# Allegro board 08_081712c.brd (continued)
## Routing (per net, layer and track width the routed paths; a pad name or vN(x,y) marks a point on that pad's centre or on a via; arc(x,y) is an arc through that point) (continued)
DAI0_PIN09_SOM_A: length 122.2
  TOP w0.127: SOMA.45 125.15,68.29 v1(125.15,68.29)
  L8_SIG w0.127: v1(217.29,98.56) 212.93,94.19 212.93,78.9 205.99,71.96 194.92,71.96 189.98,67.02 126.48,67.02 v1(125.15,68.29)
  BOTTOM w0.14: v1(217.29,98.56) 217.29,101.16 218.98,102.85 U36.13
DAI0_PIN09_SOM_B: length 68.2
  TOP w0.127: SOMB.45 v1(252.15,64.27)
  L3_SIG w0.127: v1(227.38,83.13) 227.38,83.13 227.38,84 226.77,84.61 226.77,93.62 219.56,100.84 219.56,101.42 v1(218.03,102.95)
  L8_SIG w0.127: v1(227.38,83.13) 227.38,81.36 233.55,75.18 240.41,75.18 244.6,70.99 244.6,63.63 246.61,61.62 250.93,61.62 252.15,62.84 v1(252.15,64.27)
  BOTTOM w0.203: v1(218.03,102.95) 218.36,102.95 218.77,103.35 U36.14
DAI0_PIN10_SOM_A: length 19.9
  TOP w0.127: SOMA.47 v1(125.64,64.78)
  BOTTOM w0.127: v1(125.64,64.78) 125.64,62.7 127.25,61.09 137.41,61.09 139.26,62.93 R1.1
DAI0_PIN10_SOM_B: length 19.9
  TOP w0.127: SOMB.47 v1(252.64,64.78)
  BOTTOM w0.127: R8.1 266.26,62.93 264.41,61.09 254.25,61.09 252.64,62.7 v1(252.64,64.78)
DAI0_PIN11_SOM_A: length 112.7
  TOP w0.127: P20.1 48.26,89.13 52.53,93.4 79.68,93.4 95.23,77.85 112.22,77.85 113.38,79.01 118.22,79.01 121.39,75.84 SOMA.30
  BOTTOM w0.127: P20.1 42.42,81.41 42.42,71.63 40.89,70.1 39.18,70.1 38.54,70.74 J4.4
DAI0_PIN11_SOM_B: length 145.7
  TOP w0.127: SOMB.30 v1(248.39,77.85)
  L8_SIG w0.127: v1(248.39,77.85) 249.58,77.85 252.4,80.68 253.35,80.68 253.92,81.25 253.92,81.58 254.54,82.2 255.32,82.2 257.83,84.71 273.43,84.71 275.69,82.45 296.8,82.45 304.85,74.4 311.2,74.4 313.37,76.58 325.95,76.58 327.45,75.08 350.98,75.08 353.89,72.18 v1(353.89,71.72)
  BOTTOM w0.127: P3.4 v1(353.89,71.72) 353.89,70.74 354.52,70.1 356.24,70.1 357.76,71.63 357.76,81.41 P39.1
DAI0_PIN12_SOM_A: length 119.4
  TOP w0.127: P20.3 46.71,83.72 46.71,88.29 52.32,93.9 79.88,93.9 95.58,78.21 111.86,78.21 113.17,79.51 118.46,79.51 121.9,76.07 SOMA.32
  BOTTOM w0.127: J4.8 37.27,70.21 38.65,68.83 41.53,68.83 43.56,70.87 43.56,77.47 P20.3
DAI0_PIN12_SOM_B: length 141.8
  TOP w0.127: SOMB.32 v1(248.9,77.11)
  L8_SIG w0.127: v1(352.62,71.72) 352.62,72.18 350.07,74.73 327.3,74.73 325.81,76.22 313.52,76.22 311.34,74.05 304.64,74.05 296.59,82.09 275.51,82.09 273.33,84.27 257.96,84.27 255.45,81.77 254.68,81.77 254.38,81.47 254.38,81.15 253.47,80.24 252.68,80.24 249.55,77.11 v1(248.9,77.11)
  BOTTOM w0.127: P39.3 358.9,77.47 358.9,70.87 356.87,68.83 353.99,68.83 352.62,70.21 v1(352.62,71.72) P3.8
DAI0_PIN13_SOM_A: length 125
  TOP w0.127: P20.5 46.21,79.14 46.21,88.5 52.12,94.4 80.09,94.4 95.9,78.59 111.54,78.59 112.96,80.01 118.7,80.01 122.39,76.31 SOMA.34
  BOTTOM w0.127: P20.5 44.7,73.53 44.7,70.23 42.04,67.56 38.13,67.56 36,69.69 J4.12
DAI0_PIN13_SOM_B: length 138.7
  TOP w0.127: SOMB.34 v1(249.39,76.45)
  L8_SIG w0.127: v1(351.35,71.72) 351.35,72.18 349.15,74.37 327.15,74.37 325.66,75.87 313.67,75.87 311.49,73.69 304.49,73.69 296.45,81.74 275.36,81.74 273.41,83.69 269.49,83.69 268.86,83.06 268.86,82.55 268.18,81.88 267.46,81.88 267.19,81.6 265.69,81.6 264.1,80.01 258.45,80.01 257.46,81 256.64,81 255.52,79.88 252.82,79.88 v1(249.39,76.45)
  BOTTOM w0.127: P39.5 360.05,73.53 360.05,70.23 357.38,67.56 353.47,67.56 351.35,69.69 v1(351.35,71.72) P3.12
DAI0_PIN14_SOM_A: length 129.4
  TOP w0.127: SOMA.36 122.9,76.52 118.83,80.59 94.61,80.59 80.3,94.9 51.91,94.9 45.71,88.7 45.71,74.56 P20.7
  BOTTOM w0.127: J4.16 34.73,69.16 37.6,66.29 42.55,66.29 P20.7
DAI0_PIN14_SOM_B: length 133.1
  TOP w0.127: SOMB.36 v1(249.9,75.82)
  L8_SIG w0.127: v1(249.9,75.82) 250.39,76.32 250.39,76.45 253.42,79.48 255.76,79.48 256.11,79.83 257.22,79.83 257.63,79.43 264.02,79.43 265.84,81.25 267.34,81.25 267.61,81.52 268.46,81.52 269.01,82.07 274.41,82.07 274.94,81.53 275.06,81.53 275.21,81.38 296.3,81.38 304.34,73.33 311.64,73.33 313.81,75.51 325.51,75.51 327.01,74.02 348.24,74.02 350.08,72.18 v1(350.08,71.72)
  BOTTOM w0.127: P39.7 357.89,66.29 352.94,66.29 350.08,69.16 v1(350.08,71.72) P3.16
DAI0_PIN15_SOM_A: length 136.8
  TOP w0.127: SOMA.38 123.39,76.73 119.23,80.9 95.01,80.9 80.51,95.4 51.7,95.4 45.21,88.91 45.21,69.98 P20.9
  BOTTOM w0.127: P20.9 44.96,66.93 43.05,65.02 37.07,65.02 33.46,68.63 J4.20
DAI0_PIN15_SOM_B: length 131.5
  TOP w0.127: SOMB.38 v1(250.39,75.11)
  L8_SIG w0.127: v1(250.39,75.11) 250.75,75.46 250.75,76.3 252.55,78.11 254.89,78.11 256.26,79.48 257.07,79.48 257.48,79.07 268.15,79.07 269.72,80.64 271.96,80.64 272.24,80.92 272.27,80.92 273.06,81.71 274.26,81.71 274.95,81.03 296.1,81.03 304.14,72.98 311.87,72.98 314.04,75.16 325.36,75.16 326.86,73.66 347.33,73.66 348.81,72.18 v1(348.81,71.72)
  BOTTOM w0.127: P39.9 360.3,66.93 358.39,65.02 352.42,65.02 348.81,68.63 v1(348.81,71.72) P3.20
DAI0_PIN16_SOM_A: length 146
  TOP w0.127: SOMA.40 123.9,76.94 119.55,81.28 95.33,81.28 80.71,95.9 51.49,95.9 44.6,89.01 44.6,65.51 P20.11
  BOTTOM w0.127: J4.24 32.19,68.11 36.55,63.75 43.05,63.75 44.96,61.85 P20.11
DAI0_PIN16_SOM_B: length 131.9
  TOP w0.127: v1(251.39,75.91) 251.39,75.42 250.9,74.92 SOMB.40
  L8_SIG w0.127: v1(251.39,75.91) 251.39,76.43 252.6,77.65 256.46,77.65 257.53,78.71 268.46,78.71 270.04,80.29 272.14,80.29 273.21,81.36 274.11,81.36 275.67,79.8 277.67,79.8 278.49,80.62 296,80.62 304,72.62 312.01,72.62 314.19,74.8 325.22,74.8 326.71,73.3 346.41,73.3 347.54,72.18 v1(347.54,71.72)
  BOTTOM w0.127: P39.11 360.3,61.85 358.39,63.75 351.89,63.75 347.54,68.11 v1(347.54,71.72) P3.24
DAI0_PIN17_SOM_A: length 156.6
  TOP w0.127: SOMA.42 124.39,77.14 119.95,81.58 95.74,81.58 80.92,96.4 51.29,96.4 44.1,89.22 44.1,60.93 P20.13
  BOTTOM w0.127: P20.13 42.55,62.48 36.02,62.48 30.92,67.58 J4.28
DAI0_PIN17_SOM_B: length 132.3
  TOP w0.127: v1(252.04,75.97) 252.04,75.54 251.39,74.89 SOMB.42
  L8_SIG w0.127: v1(252.04,75.97) 252.04,76.49 252.64,77.09 252.94,77.09 252.95,77.1 260.24,77.1 261.49,78.36 268.61,78.36 270.18,79.93 272.29,79.93 273.35,81 273.97,81 275.54,79.43 277.8,79.43 278.64,80.26 295.86,80.26 303.85,72.27 312.16,72.27 312.84,72.94 345.5,72.94 346.27,72.18 v1(346.27,71.72)
  BOTTOM w0.127: P3.28 v1(346.27,71.72) 346.27,67.58 351.36,62.48 357.89,62.48 P39.13
DAI0_PIN18_SOM_A: length 169
  TOP w0.127: SOMA.44 124.9,77.35 120.36,81.89 96.14,81.89 81.13,96.9 51.08,96.9 43.6,89.42 43.6,56.35 P20.15
  BOTTOM w0.127: J4.32 29.65,67.05 35.5,61.21 41.78,61.21 46.36,56.64 46.36,53.59 P20.15
DAI0_PIN18_SOM_B: length 133.9
  TOP w0.127: v1(252.74,76) 252.74,75.55 251.9,74.7 SOMB.44
  L8_SIG w0.127: v1(252.74,76) 252.74,76.38 253.1,76.75 264.71,76.75 265.89,77.93 268.68,77.93 270.33,79.58 273.51,79.58 274.29,78.79 294.34,78.79 301.21,71.91 312.31,71.91 312.98,72.59 344.59,72.59 345,72.18 v1(345,71.72)
  BOTTOM w0.127: P3.32 v1(345,71.72) 345,67.05 350.84,61.21 357.12,61.21 361.7,56.64 361.7,53.59 P39.15
DAI0_PIN19_SOM_A: length 140.6
  TOP w0.127: SOMA.46 v1(125.39,74.95) ; v1(17.23,31.62) 32.22,46.61 P20.17
  BOTTOM w0.127: v1(125.39,74.95) 124.34,73.89 100.93,73.89 100.34,73.3 100.3,73.3 64.01,37.01 51.41,37.01 50.29,38.13 50.29,44.58 P20.17
  BOTTOM w0.14: U67.4 v1(17.23,31.62)
DAI0_PIN19_SOM_A_A2B: length 49
  L8_SIG w0.127: v1(28.38,63.93) 28.38,40.07 20.8,32.49 17.09,32.49 v1(16.72,32.12)
  BOTTOM w0.127: J4.36 v1(28.38,63.93)
  BOTTOM w0.14: U67.3 v1(16.72,32.12)
DAI0_PIN19_SOM_B: length 153.6
  TOP w0.127: v1(384.89,31.62) 384.89,32.58 369.65,47.83 364.82,47.83 P39.17 ; SOMB.46 v1(252.39,72.03)
  L8_SIG w0.127: P39.17 361.39,48.82 290.95,48.82 273.1,66.67 258.47,66.67 253.14,72.01 252.41,72.01 v1(252.39,72.03)
  BOTTOM w0.14: U69.4 v1(384.89,31.62)
DAI0_PIN19_SOM_B_A2B: length 64.2
  TOP w0.127: v1(384.39,32.12) 381.24,32.12 368,45.36 361.92,45.36 343.73,63.56 v1(343.73,71.72)
  BOTTOM w0.127: P3.36 v1(343.73,71.72)
  BOTTOM w0.14: U69.3 v1(384.39,32.12)
DAI0_PIN20_SOM_A: length 146.7
  TOP w0.127: SOMA.48 v1(125.9,75.45) ; P20.19 29.06,41.53 18.11,30.58 15.7,30.58 14.58,29.46 10.85,29.46 10.34,29.97 v1(9.52,29.97)
  BOTTOM w0.127: v1(125.9,75.45) 125.9,74.51 124.89,73.51 101.51,73.51 64.3,36.3 51.28,36.3 49.71,37.87 49.71,40.08 P20.19
  BOTTOM w0.14: v1(9.52,29.97) 9.88,29.62 U67.9
DAI0_PIN20_SOM_A_A2B: length 62.7
  L8_SIG w0.127: v1(27.11,64.61) 28.48,64.61 29.41,63.68 29.41,39.42 16.21,26.21 13.18,26.21 11.47,27.92 v1(11.47,30.12)
  BOTTOM w0.127: J4.40 v1(27.11,64.61)
  BOTTOM w0.14: U67.10 v1(11.47,30.12)
DAI0_PIN20_SOM_B: length 148.4
  TOP w0.127: P39.19 364.87,40.26 369.27,40.26 376.05,33.48 376.05,31.11 v1(377.19,29.97) ; SOMB.48 v1(252.9,71.38)
  L8_SIG w0.127: v1(252.9,71.38) 257.98,66.29 272.69,66.29 273.6,65.39 273.6,64.42 275.03,62.99 276,62.99 290.68,48.31 356.82,48.31 P39.19
  BOTTOM w0.14: v1(377.19,29.97) 377.54,29.62 U69.9
DAI0_PIN20_SOM_B_A2B: length 62.3
  TOP w0.127: v1(342.46,71.72) 342.46,63.26 362.84,42.88 368.21,42.88 379.14,31.95 v1(379.14,30.12)
  BOTTOM w0.127: P3.40 v1(342.46,71.72)
  BOTTOM w0.14: U69.10 v1(379.14,30.12)
DAI1_PIN01_SOM_A: length 53.4
  TOP w0.127: SOMA.51 v1(126.64,63.76)
  BOTTOM w0.127: U38.3 110.36,96.16 110.24,96.04 110.24,94.74 112.39,92.58 120.4,92.58 128.02,84.96 129.92,84.96 132.53,82.35 132.53,73.22 127.61,68.31 127.61,64.24 127.14,63.76 v1(126.64,63.76)
DAI1_PIN01_SOM_B: length 222.3
  TOP w0.127: v1(248.77,60.92) 250.46,60.92 253.64,64.11 SOMB.51
  L8_SIG w0.127: 243.48,62.1 244.67,60.92 v1(248.77,60.92)
  L8_SIG w0.14: v1(112.04,95.96) 111.36,96.64 111.36,98.8 112.85,100.29 116.35,100.29 116.96,100.89 131.96,100.89 133.69,99.16 165.65,99.16 173.6,107.11 229.04,107.11 229.51,106.63 237.23,106.63 243.25,100.61 243.25,92.23 241.67,90.65 240.58,90.65 239.52,89.59 232.71,89.59 226.49,83.36 226.49,76.02 227.69,74.82 240.24,74.82 243.48,71.58 243.48,62.1
  BOTTOM w0.14: U38.2 111.74,95.66 v1(112.04,95.96)
DAI1_PIN02_SOM_A: length 52.6
  TOP w0.127: SOMA.53 v1(127.15,64.85)
  BOTTOM w0.127: v1(127.15,64.85) 127.15,68.47 132.08,73.41 132.08,82.17 129.67,84.58 127.76,84.58 120.14,92.2 112.14,92.2 109.6,94.74 109.6,97.41 109.86,97.66 U38.6
DAI1_PIN02_SOM_B: length 220.9
  TOP w0.127: v1(249.57,60.42) 250.5,60.42 254.15,64.06 SOMB.53
  L8_SIG w0.127: v1(249.57,60.42) 244.65,60.42 243.12,61.96 243.12,62.1
  L8_SIG w0.14: 243.12,62.1 243.12,71.43 240.09,74.45 227.54,74.45 226.12,75.87 226.12,83.52 232.56,89.95 239.26,89.95 240.32,91.01 241.35,91.01 242.89,92.55 242.89,100.46 237.46,105.88 231.29,105.88 230.73,105.32 228.57,105.32 227.16,106.74 173.94,106.74 165.86,98.66 133.67,98.66 131.87,100.46 117.21,100.46 116.55,99.79 113.15,99.79 111.91,98.55 v1(111.91,97.16)
  BOTTOM w0.14: U38.5 v1(111.91,97.16)
DAI1_PIN03_SOM_A: length 46.6
  TOP w0.127: SOMA.55 v1(127.64,63.25)
  BOTTOM w0.127: U39.13 131.52,96.66 128.4,93.54 128.4,89.03 129.79,87.63 131.7,87.63 135.38,83.95 135.38,70.48 130.94,66.04 130.94,64.9 129.67,63.63 128.03,63.63 v1(127.64,63.25)
DAI1_PIN03_SOM_B: length 197.9
  TOP w0.127: SOMB.55 254.64,63.85 250.71,59.92 v1(248.77,59.92)
  L8_SIG w0.127: 242.75,62.1 242.75,61.82 244.65,59.92 v1(248.77,59.92)
  L8_SIG w0.14: 242.75,62.1 242.75,71.27 239.94,74.09 227.39,74.09 225.75,75.72 225.75,83.84 233.14,91.23 239.73,91.23 242.52,94.02 242.52,100.31 237.31,105.51 232.07,105.51 231.41,104.85 225.33,104.85 224.56,105.61 218.2,105.61 217.49,106.32 174.23,106.32 166.2,98.29 135.5,98.29 133.71,96.49 v1(133.21,96.49)
  BOTTOM w0.14: U39.14 132.88,96.16 v1(133.21,96.49)
DAI1_PIN04_SOM_A: length 53
  TOP w0.127: SOMA.57 v1(128.15,64.27)
  BOTTOM w0.127: v1(128.15,64.27) 128.15,68.07 132.97,72.9 132.97,82.55 130.17,85.34 128.14,85.34 120.52,92.96 113.54,92.96 112.78,93.73 112.78,97.51 113.43,98.16 U38.10
DAI1_PIN04_SOM_B: length 220.4
  TOP w0.127: v1(249.57,59.42) 250.92,59.42 255.15,63.65 SOMB.57
  L8_SIG w0.127: v1(249.57,59.42) 244.65,59.42 242.38,61.69 242.38,62.1
  L8_SIG w0.14: v1(113.68,97.66) 114.97,98.96 121.77,98.96 122.13,99.32 129.6,99.32 132.98,95.94 133.89,95.94 135.87,97.92 166.54,97.92 174.56,105.95 217.34,105.95 218.04,105.24 224.41,105.24 225.18,104.48 231.56,104.48 232.22,105.14 237.16,105.14 242.15,100.15 242.15,94.17 239.58,91.6 232.89,91.6 225.39,84.1 225.39,75.57 227.24,73.72 239.78,73.72 242.38,71.12 242.38,62.1
  BOTTOM w0.14: U38.11 v1(113.68,97.66)
DAI1_PIN05_SOM_A: length 50.3
  TOP w0.127: SOMA.59 v1(128.64,64.78)
  BOTTOM w0.127: U38.13 113.45,96.66 113.16,96.37 113.16,93.98 113.79,93.34 120.78,93.34 128.4,85.72 130.43,85.72 133.42,82.74 133.42,72.61 128.64,67.84 v1(128.64,64.78)
DAI1_PIN05_SOM_B: length 219.9
  TOP w0.127: v1(248.77,58.92) 251.13,58.92 255.64,63.44 SOMB.59
  L8_SIG w0.127: 242.01,62.1 242.01,61.56 244.65,58.92 v1(248.77,58.92)
  L8_SIG w0.14: 242.01,62.1 242.01,70.97 239.63,73.35 227.08,73.35 225.02,75.41 225.02,84.25 232.74,91.97 238.17,91.97 240.82,94.61 240.82,98.2 240.02,99 240.02,101.76 237.01,104.77 232.38,104.77 231.71,104.11 225.03,104.11 224.29,104.85 190.91,104.85 190.88,104.88 174.47,104.88 167.08,97.49 135.95,97.49 134.04,95.57 132.7,95.57 129.32,98.95 126.01,98.95 125.15,98.09 121.01,98.09 120.73,98.37 118.77,98.37 117.98,97.59 115.1,97.59 v1(113.68,96.16)
  BOTTOM w0.14: U38.14 v1(113.68,96.16)
DAI1_PIN06_SOM_A: length 44.3
  TOP w0.127: SOMA.61 v1(129.15,64.27)
  BOTTOM w0.127: v1(129.15,64.27) 129.73,64.27 130.3,64.85 130.3,66.17 135,70.87 135,83.69 131.44,87.25 129.54,87.25 128.02,88.77 128.02,93.34 124.97,96.39 124.97,97.41 124.74,97.64 U40.3
DAI1_PIN06_SOM_B: length 209.4
  TOP w0.127: SOMB.61 256.15,63.23 251.33,58.42 v1(249.57,58.42)
  L8_SIG w0.127: v1(249.57,58.42) 244.64,58.42 241.64,61.42 241.64,62.1
  L8_SIG w0.14: v1(125.48,96.65) 127.43,96.65 128.51,97.73 130.02,97.73 132.54,95.21 134.2,95.21 136.11,97.12 167.23,97.12 174.59,104.48 224.14,104.48 224.87,103.74 231.86,103.74 232.53,104.41 236.85,104.41 239.65,101.61 239.65,98.59 240.45,97.79 240.45,94.77 238.02,92.34 232.57,92.34 224.65,84.42 224.65,75.26 226.93,72.98 239.48,72.98 241.64,70.82 241.64,62.1
  BOTTOM w0.14: v1(125.48,96.65) 125.48,97.66 125,98.14 U40.2
DAI1_PIN07_SOM_A: length 40.7
  TOP w0.127: SOMA.63 v1(129.64,64.85)
  BOTTOM w0.127: v1(129.64,64.85) 129.64,66.27 134.62,71.25 134.62,83.44 131.19,86.87 129.29,86.87 127.64,88.52 127.64,93.09 124.59,96.14 U40.6
DAI1_PIN07_SOM_B: length 205.9
  TOP w0.127: v1(248.77,57.92) 251.54,57.92 256.64,63.03 SOMB.63
  L8_SIG w0.127: 241.27,62.1 241.27,61.29 244.64,57.92 v1(248.77,57.92)
  L8_SIG w0.14: v1(122.91,96.64) 126.44,93.11 135.93,93.11 136.84,94.01 165.73,94.01 172.02,100.3 236.21,100.3 239.03,97.49 239.5,97.49 240.08,96.9 240.08,94.92 237.86,92.7 232.39,92.7 224.28,84.6 224.28,75.11 226.78,72.61 239.33,72.61 241.27,70.66 241.27,62.1
  BOTTOM w0.14: U40.5 v1(122.91,96.64)
DAI1_PIN08_SOM_A: length 39.8
  TOP w0.127: SOMA.65 v1(130.15,67.62)
  BOTTOM w0.127: v1(130.15,67.62) 134.24,71.72 134.24,83.19 130.94,86.49 128.91,86.49 121.16,94.23 120.02,94.23 119.47,94.78 119.47,95.47 119.64,95.64 U40.10
DAI1_PIN08_SOM_B: length 207
  TOP w0.127: v1(249.55,57.45) 251.78,57.45 257.15,62.82 SOMB.65
  L8_SIG w0.127: v1(249.55,57.45) 244.61,57.45 240.91,61.15 240.91,62.1
  L8_SIG w0.14: 240.91,62.1 240.91,70.51 239.17,72.24 226.62,72.24 223.91,74.96 223.91,84.82 232.16,93.07 237.6,93.07 238.54,94.01 238.54,97.33 235.93,99.93 172.18,99.93 165.89,93.64 137.08,93.64 136.18,92.74 124.54,92.74 v1(121.15,96.14)
  BOTTOM w0.14: U40.11 v1(121.15,96.14)
DAI1_PIN09_SOM_A: length 41.5
  TOP w0.127: v1(130.17,68.45) 130.64,67.98 SOMA.67
  BOTTOM w0.127: v1(130.17,68.45) 133.86,72.14 133.86,82.93 130.68,86.11 128.65,86.11 120.9,93.85 119.89,93.85 119,94.74 119,96.65 119.49,97.14 U40.13
DAI1_PIN09_SOM_B: length 210.2
  TOP w0.127: v1(248.82,56.9) 251.93,56.9 257.64,62.61 SOMB.67
  L8_SIG w0.127: v1(248.82,56.9) 244.66,56.9 240.54,61.02 240.54,62.1
  L8_SIG w0.14: v1(119.51,97.64) 119.51,97 124.17,92.33 136.42,92.33 137.27,93.17 165.94,93.17 171.95,99.19 236.07,99.19 238.17,97.08 238.17,94.2 237.41,93.44 232.01,93.44 223.54,84.98 223.54,74.8 226.47,71.88 239.02,71.88 240.54,70.36 240.54,62.1
  BOTTOM w0.14: U40.14 v1(119.51,97.64)
DAI1_PIN10_SOM_A: length 97.9
  TOP w0.127: SOMA.69 v1(131.15,64.27) ; v1(180.84,121.41) 180.52,121.72 U81.10
  BOTTOM w0.127: v1(131.15,64.27) 131.15,63.83 131.44,63.53 132.71,63.53 133.12,63.93 133.12,66.22 140.92,74.02 145.19,74.02 146.3,75.13 146.3,76.71 148.46,78.87 148.46,88.87 149.33,89.74 149.33,110.77 159.23,120.68 180.1,120.68 v1(180.84,121.41)
DAI1_PIN10_SOM_B: length 136.9
  TOP w0.127: v1(180.84,119.89) 180.12,120.6 U81.9 ; SOMB.69 v1(258.15,64.27)
  L8_SIG w0.127: v1(258.15,64.27) 257.27,64.27 250.7,70.84 250.7,74.03 244.52,80.21 239.01,80.21 238.88,80.34 238.88,82.29 240.07,83.48 245.17,83.48 v1(250.28,88.58)
  BOTTOM w0.127: v1(180.84,119.89) 183.63,117.09 196.57,117.09 212.09,101.57 212.09,96.01 212.42,95.68 230.86,95.68 233.22,98.04 241.88,98.04 242.42,97.51 242.42,96.45 v1(250.28,88.58)
DAI1_PIN11_SOM_A: length 103.5
  TOP w0.127: SOMA.52 v1(126.9,75.45)
  L8_SIG w0.127: v1(91.25,71.72) 91.67,71.3 100.03,71.3 103.02,74.3 114.99,74.3 117.47,76.78 125.56,76.78 v1(126.9,75.45)
  BOTTOM w0.127: P21.1 54.61,41.91 54.61,49.53 61.34,56.26 82.14,56.26 91.25,65.37 v1(91.25,71.72) J5.4
DAI1_PIN11_SOM_B: length 201.1
  TOP w0.127: SOMB.52 v1(253.9,75.38)
  L8_SIG w0.127: P40.1 365.61,37.57 363.09,37.57 353.39,47.27 289.44,47.27 272.86,63.85 272.86,65.12 272.43,65.56 256.85,65.56 251.26,71.16 251.26,72.74 v1(253.9,75.38)
  BOTTOM w0.127: P4.4 406.59,65.37 397.48,56.26 376.68,56.26 369.95,49.53 369.95,41.91 P40.1
DAI1_PIN12_SOM_A: length 97.8
  TOP w0.127: SOMA.54 v1(127.39,74.95)
  L8_SIG w0.127: v1(127.39,74.95) 126.34,73.89 103.23,73.89 99.67,70.33 v1(89.98,70.33)
  BOTTOM w0.127: P21.3 53.59,45.97 53.59,49.78 61.34,57.53 81.62,57.53 89.98,65.89 v1(89.98,70.33) J5.8
DAI1_PIN12_SOM_B: length 194.1
  TOP w0.127: SOMB.54 v1(254.39,74.87)
  L8_SIG w0.127: v1(254.39,74.87) 251.76,72.24 251.76,71.65 257.51,65.91 272.57,65.91 273.22,65.27 273.22,64.09 274.83,62.48 275.46,62.48 290.17,47.78 354.08,47.78 361.57,40.28 364.87,40.28 365.35,40.77 365.35,42.39 P40.3
  BOTTOM w0.127: P4.8 405.32,65.89 396.96,57.53 376.68,57.53 368.94,49.78 368.94,45.97 P40.3
DAI1_PIN13_SOM_A: length 95.5
  TOP w0.127: SOMA.56 v1(127.9,75.45)
  L8_SIG w0.127: v1(88.71,71.72) 88.71,72.18 89.12,72.59 100.58,72.59 102.64,74.65 114.81,74.65 117.35,77.19 126.16,77.19 v1(127.9,75.45)
  BOTTOM w0.127: J5.12 v1(88.71,71.72) 88.71,66.42 81.09,58.8 61.34,58.8 P21.5
DAI1_PIN13_SOM_B: length 175.5
  TOP w0.127: SOMB.56 v1(254.9,71.45)
  L8_SIG w0.127: P40.5 365.91,50.27 363.14,50.27 362.25,49.38 291.03,49.38 273.23,67.18 258.7,67.18 254.9,70.99 v1(254.9,71.45)
  BOTTOM w0.127: P40.5 376.68,58.8 396.43,58.8 404.05,66.42 P4.12
DAI1_PIN14_SOM_A: length 91.9
  TOP w0.127: SOMA.58 v1(128.39,74.95)
  L8_SIG w0.127: v1(87.44,69.79) 99.78,69.79 103.5,73.51 126.96,73.51 v1(128.39,74.95)
  BOTTOM w0.127: J5.16 v1(87.44,69.79) 87.44,66.95 80.56,60.07 61.34,60.07 55.5,54.23 P21.7
DAI1_PIN14_SOM_B: length 172
  TOP w0.127: SOMB.58 v1(255.39,72.03)
  L8_SIG w0.127: v1(255.39,72.03) 255.65,71.77 255.65,70.87 258.88,67.64 273.35,67.64 291.13,49.86 357.58,49.86 360.53,52.81 365.61,52.81 P40.7
  BOTTOM w0.127: P4.16 402.78,66.95 395.91,60.07 376.68,60.07 370.84,54.23 P40.7
DAI1_PIN15_SOM_A: length 92.2
  TOP w0.127: SOMA.60 v1(128.9,75.45)
  L8_SIG w0.127: v1(128.9,75.45) 126.68,77.67 117.33,77.67 114.79,75.13 102.62,75.13 100.49,73 86.69,73 86.17,72.48 v1(86.17,71.72)
  BOTTOM w0.127: J5.20 v1(86.17,71.72) 86.17,67.47 80.04,61.34 61.34,61.34 59.31,59.31 P21.9
DAI1_PIN15_SOM_B: length 174.3
  TOP w0.127: SOMB.60 v1(255.9,75.38)
  L8_SIG w0.127: P40.9 365.38,57.66 365.38,56.64 364.08,55.35 362.31,55.35 357.38,50.42 291.47,50.42 279.65,62.23 279.65,63.04 274.57,68.12 259.16,68.12 256.01,71.27 256.01,73.94 255.65,74.3 255.65,75.13 v1(255.9,75.38)
  BOTTOM w0.127: P40.9 374.65,59.31 376.68,61.34 395.38,61.34 401.51,67.47 P4.20
DAI1_PIN16_SOM_A: length 89.4
  TOP w0.127: SOMA.62 v1(129.39,74.95)
  L8_SIG w0.127: v1(84.9,69.27) 84.92,69.24 99.95,69.24 103.84,73.13 127.57,73.13 v1(129.39,74.95)
  BOTTOM w0.127: J5.24 v1(84.9,69.27) 84.9,68.75 78.77,62.61 60.96,62.61 59.18,64.39 P21.11
DAI1_PIN16_SOM_B: length 174.8
  TOP w0.127: SOMB.62 v1(256.39,74.87)
  L8_SIG w0.127: P40.11 365.84,63.2 363.17,63.2 361.87,61.9 361.87,55.68 357.2,51 291.52,51 281.18,61.34 281.18,62.15 274.82,68.5 259.79,68.5 256.39,71.9 v1(256.39,74.87)
  BOTTOM w0.127: P40.11 374.52,64.39 376.3,62.61 394.85,62.61 400.24,68 P4.24
DAI1_PIN17_SOM_A: length 14.3
  TOP w0.127: SOMA.64 v1(129.9,76.2)
  BOTTOM w0.127: v1(129.9,76.2) 128.63,77.47 123.95,77.47 121.17,80.26 R400.1
DAI1_PIN17_SOM_A_A2B: length 88.4
  L8_SIG w0.127: v1(125.03,80.97) 125.03,80.05 123.8,78.82 114.63,78.82 113.26,77.44 101.5,77.44 98.96,74.9 85.6,74.9 83.63,72.94 v1(83.63,71.72)
  BOTTOM w0.127: P21.13 55.37,69.47 61.32,63.53 77.24,63.53 83.63,69.91 v1(83.63,71.72) J5.28 ; U45.3 v1(125.03,80.97)
DAI1_PIN17_SOM_B: length 14.3
  TOP w0.127: SOMB.64 v1(256.9,76.2)
  BOTTOM w0.127: v1(256.9,76.2) 255.85,77.24 251.18,77.24 248.17,80.26 R412.2
DAI1_PIN17_SOM_B_A2B: length 199.2
  TOP w0.127: v1(320.65,90.32) 333.27,90.32 333.88,89.71 358.8,89.71 360.94,91.85 367.51,91.85 370.13,89.23 370.13,72.57 P40.13
  L8_SIG w0.127: v1(251.33,80.97) 250.78,81.52 250.78,83.7 251.1,84.02 251.55,84.02 251.75,83.82 252.94,83.82 253,83.88 253.87,83.88 254.12,84.12 254.19,84.12 254.42,84.36 255.46,84.36 257.24,86.13 275.55,86.13 277.81,83.87 297.94,83.87 304.57,77.24 309.62,77.24 310.79,78.42 310.79,81.1 320.01,90.32 v1(320.65,90.32)
  BOTTOM w0.127: P4.28 398.97,68.53 394.33,63.88 376.3,63.88 370.71,69.47 P40.13 ; U47.3 v1(251.33,80.97)
DAI1_PIN18_SOM_A: length 16.7
  TOP w0.127: SOMA.66 v1(130.39,74.87)
  BOTTOM w0.127: R401.1 120.4,82.22 120.4,80.26 123.7,76.96 128.3,76.96 v1(130.39,74.87)
DAI1_PIN18_SOM_A_A2B: length 89.7
  L8_SIG w0.127: v1(124.49,82.47) 124.49,80.19 123.47,79.17 114.45,79.17 113.11,77.83 101.27,77.83 98.86,75.41 84.58,75.41 82.36,73.19 v1(82.36,71.72)
  BOTTOM w0.127: J5.32 v1(82.36,71.72) 82.36,70.02 77.42,65.07 61.16,65.07 P21.15 ; U45.6 v1(124.49,82.47)
DAI1_PIN18_SOM_B: length 16.7
  TOP w0.127: SOMB.66 v1(257.39,74.87)
  BOTTOM w0.127: v1(257.39,74.87) 255.38,76.89 250.77,76.89 247.4,80.26 247.4,82.22 R413.2
DAI1_PIN18_SOM_B_A2B: length 189.1
  TOP w0.127: P40.15 369.57,77.09 369.57,89.13 367.31,91.39 361.13,91.39 358.87,89.12 333.82,89.12 333.27,89.66 v1(320.65,89.66)
  L8_SIG w0.127: v1(320.65,89.66) 320.08,89.66 311.28,80.86 311.28,78.24 309.92,76.89 304.32,76.89 297.69,83.52 277.66,83.52 275.4,85.78 257.38,85.78 255.61,84 254.57,84 254.34,83.77 254.26,83.77 254.02,83.52 253.15,83.52 252.94,83.31 252.86,83.31 252.02,82.47 v1(251.33,82.47)
  BOTTOM w0.127: P40.15 376.43,65.15 393.8,65.15 397.7,69.05 P4.32 ; U47.6 v1(251.33,82.47)
DAI1_PIN19_SOM_A: length 11.1
  TOP w0.127: SOMA.68 v1(130.9,75.45)
  BOTTOM w0.127: R402.1 131.57,81.46 131.57,76.13 v1(130.9,75.45)
DAI1_PIN19_SOM_A_A2B: length 95.5
  L8_SIG w0.127: v1(81.09,71.72) 81.09,72.96 84.02,75.9 98.71,75.9 101.02,78.21 112.98,78.21 114.33,79.55 123.14,79.55 123.83,80.24 123.83,82.93 124.26,83.36 125.98,83.36 v1(126.37,82.97)
  BOTTOM w0.127: P21.17 53.34,77.98 53.34,74.42 61.87,65.89 76.84,65.89 81.09,70.14 v1(81.09,71.72) J5.36 ; U45.10 v1(126.37,82.97)
DAI1_PIN19_SOM_B: length 11.1
  TOP w0.127: SOMB.68 v1(257.9,75.45)
  BOTTOM w0.127: R414.2 258.57,81.46 258.57,76.13 v1(257.9,75.45)
DAI1_PIN19_SOM_B_A2B: length 181.8
  TOP w0.127: P40.17 369.06,81.66 369.06,88.9 367.2,90.76 361.39,90.76 359.13,88.49 333.56,88.49 333.05,89 v1(320.65,89)
  L8_SIG w0.127: v1(320.65,89) 320.12,89 311.71,80.59 311.71,78.17 310.07,76.53 304,76.53 297.38,83.16 277.52,83.16 275.25,85.42 257.53,85.42 255.76,83.65 254.72,83.65 254.48,83.41 254.41,83.41 253.97,82.97 v1(253.37,82.97)
  BOTTOM w0.127: P40.17 368.68,77.98 368.68,74.42 376.68,66.42 393.27,66.42 396.43,69.58 P4.36 ; U47.10 v1(253.37,82.97)
DAI1_PIN20_SOM_A: length 9.3
  TOP w0.127: v1(130.94,76.2) 131.39,75.74 SOMA.70
  BOTTOM w0.127: v1(130.94,76.2) 130.94,80.57 R403.1
DAI1_PIN20_SOM_A_A2B: length 102.3
  L8_SIG w0.127: v1(126.37,81.47) 127.05,82.15 127.05,83.46 126.64,83.87 124,83.87 123.29,83.16 123.29,80.37 122.83,79.91 114.18,79.91 112.86,78.59 100.81,78.59 98.53,76.3 82.93,76.3 79.82,73.19 v1(79.82,71.72)
  BOTTOM w0.127: U45.13 v1(126.37,81.47) ; J5.40 v1(79.82,71.72) 79.82,70.35 76.2,66.73 62.31,66.73 54.48,74.55 54.48,81.91 P21.19
DAI1_PIN20_SOM_B: length 9.3
  TOP w0.127: SOMB.70 258.39,75.74 v1(257.94,76.2)
  BOTTOM w0.127: v1(257.94,76.2) 257.94,80.57 R415.2
DAI1_PIN20_SOM_B_A2B: length 177.8
  TOP w0.127: v1(320.65,88.34) 332.59,88.34 333.05,87.88 359.64,87.88 361.72,89.97 367.24,89.97 368.68,88.53 368.68,86.36 P40.19
  L8_SIG w0.127: v1(253.37,81.47) 253.37,81.87 254.56,83.06 254.63,83.06 254.86,83.29 255.91,83.29 257.68,85.06 275.11,85.06 277.37,82.8 297.15,82.8 303.83,76.12 310.24,76.12 312.12,78 312.12,80.34 320.12,88.34 v1(320.65,88.34)
  BOTTOM w0.127: U47.13 v1(253.37,81.47) ; P40.19 369.82,81.91 369.82,74.55 376.68,67.69 392.75,67.69 395.16,70.1 P4.40
DAI1_ROUTE: length 271.7
  TOP w0.127: U8.12 27.58,112.99 v1(26.67,112.08) R512.1
  L3_SIG w0.127: v1(249.22,79.97) 246.01,79.97 240.08,74.04 217.6,74.04 211.37,80.28 195.87,80.28 192.92,83.22 157.94,83.22 154.35,79.63 150.66,79.63 149.89,78.86 149.89,78.86 149.84,78.82 147.94,78.82 146.41,77.29 138.56,77.29 138.44,77.18 133.31,77.18 132.11,78.38 123.77,78.38 121.97,80.19 121.97,85.6 123.27,86.89 v1(123.27,88.19)
  L8_SIG w0.127: v1(123.27,88.19) 119.3,92.15 113.19,92.15 109.86,95.49 109.86,96.77 106.3,100.33 66.55,100.33 56.52,110.36 26.19,110.36 25.83,110.72 25.83,111.81 26.1,112.08 v1(26.67,112.08)
  BOTTOM w0.127: R512.1 v1(26.67,112.08) ; v1(123.27,88.19) 125.6,85.85 125.6,80.26 125.31,79.97 U45.1 ; U47.1 v1(249.22,79.97)
E70_3V3: length 67.7
  TOP w0.14: DS20.A v1(197.61,26.01) ; R484.1 v1(190.88,28.6) ; R485.1 v1(196.21,29.11)
  TOP w0.203: U58.3 U58.2 213.38,33.9 213.18,34.1 U58.1 211.72,34.1 C367.1 ; U59.1 219.76,20.67 219.56,20.46 v1(219.13,20.46) ; U55.3 v1(224.03,12.26) ; U59.7 219.76,23.62 C363.1 ; U59.10 218.64,21.51 218.44,21.3 v1(218.44,20.64)
  TOP w0.305: R484.1 191.45,29.21 192.22,28.44 U56.4 192.74,28.44 193.05,28.14 C353.1 ; R466.1 v1(196.81,35.62) ; R469.1 v1(208.06,35.62) ; R467.1 v1(196.81,34.35) ; U53.8 C325.1 206.51,36.97 ; R464.1 v1(196.81,36.89) ; R470.1 v1(199.78,14.77)
  TOP w0.508: P29.1 200.54,29.65 C322.1 ; C353.1 v1(192.3,26.86) ; D12.4 193.09,21.49 C321.1 v1(192.3,21.53) ; R486.1 v1(216.83,12.26) ; TP24.1 227.18,6.29 ; TP24.1 226.06,7.4 ; TP24.1 224.94,6.29 ; v1(206.51,38.82) C326.1 206.51,36.97 ; R475.1 v1(205.61,14.61) ; R471.1 v1(198.62,23.94) ; P10.1 v1(227.2,19.11) ; C355.1 v1(218.87,15.05) ; C367.1 v1(210.67,33.84) ; P34.1 v1(192.02,7.28) ; R468.1 v1(198.62,22.8) ; C363.1 v1(219.45,24.8)
  L5_PWR w0.508: 224.94,6.29 TP24.1 ; TP24.1 226.06,7.4 ; TP24.1 227.18,6.29 ; TP24.1 226.06,5.17 ; P29.1 201.71,29.65 ; P29.1 199.35,29.65 ; P29.1 200.53,28.47 ; P29.1 200.53,30.84 ; 193.04,22.88 P28.2 ; P28.2 193.04,25.25 ; P28.2 194.22,24.07 ; P28.2 191.86,24.07
  BOTTOM w0.203: C348.1 209.68,18.28 v2(209.05,18.91) ; C354.1 206.63,23.52 206.63,21.91 206.83,21.71 v2(207.05,21.71) ; C364.1 194.93,37.53 U60.1 ; v2(207.05,19.31) 207.05,19.92 C346.1
  BOTTOM w0.508: v1(204.84,14.59) C352.1 C358.1 ; C349.1 C348.1 C350.1 ; E3.1 210.7,21.63 C324.1 C357.1 v1(210.03,23.69) ; C364.1 v1(195.91,37.27)
  vias: v2(205.45,20.11) v2(207.84,19.31) v2(207.84,18.51)
E70_FLASH_CS_N: length 24.6
  TOP w0.14: R464.2 v1(198.67,36.89) U53.1
  L3_SIG w0.114: v2(205.45,22.91) 205.45,24.17 204.85,24.77 204.85,29.08 206.88,31.12 206.88,31.81 206.44,32.26 200.53,32.26 199.17,33.62 198.34,33.62 197.99,33.97 197.99,36.22 v1(198.67,36.89)
E70_FLASH_D2: length 31.2
  TOP w0.14: R467.2 v1(198.67,34.35) U53.3
  L3_SIG w0.114: v1(198.67,34.35) 204.03,34.35 205.87,36.2 206.73,36.2 207.26,35.66 207.26,34.04 211.82,29.48 211.82,25.65 211.07,24.9 208.67,24.9 207.39,23.62 207.39,22.58 208.15,21.82 208.15,21.62 v2(207.84,21.31)
E70_FLASH_D3: length 24.4
  TOP w0.14: R469.2 v1(206.21,35.62) U53.7
  L3_SIG w0.114: v1(206.21,35.62) 205.49,34.9 205.49,34.1 207.64,31.94 207.64,30.1 206.12,28.57 206.12,27.18 205.49,26.54 205.49,25.15 206.63,24 206.63,21.4 207.01,21.02 207.94,21.02 208.19,21.27 209.07,21.27 209.41,20.93 209.41,19.61 209.17,19.37 208.7,19.37 v2(208.24,18.91)
E70_FLASH_MISO: length 12.1
  TOP w0.14: v1(206.25,31.43) 206.25,32.78 205.94,33.08 U53.5
  L3_SIG w0.114: v1(206.25,31.43) 204.34,29.53 204.34,24.57 205.05,23.87 v2(205.05,22.91)
E70_FLASH_MOSI: length 31
  TOP w0.14: U53.2 v1(198.67,35.62) R466.2
  L3_SIG w0.114: v2(207.84,22.51) 208.28,22.95 208.28,23.88 208.81,24.41 211.48,24.41 212.34,25.27 212.34,29.85 209.04,33.15 209.04,35.69 208.57,36.16 207.55,36.16 206.88,36.83 205.36,36.83 204.15,35.62 v1(198.67,35.62)
E70_FLASH_SCK: length 15.6
  TOP w0.14: U53.6 v1(206.21,34.35) R465.1
  L3_SIG w0.114: v2(207.05,22.51) 207.05,24.62 206.22,25.44 206.22,26.27 206.76,26.8 206.76,27.94 208.41,29.59 208.41,32.16 v1(206.21,34.35)
E70_RESET_N: length 44.1
  TOP w0.114: R487.2 197.53,30.92 196.96,30.35 R485.2 194.56,30.35 U56.2
  TOP w0.14: R487.2 v1(198.44,30.92) ; v1(198.41,15.51) R470.2 197.59,14.77 197.1,14.29 P34.10
  L8_SIG w0.114: v1(198.41,15.51) 197.19,14.29 191.9,14.29 191.48,14.7 191.48,15.43 196.57,20.51 202.82,20.51 204.02,21.71 v2(204.65,21.71)
  BOTTOM w0.114: v2(204.65,21.71) 204.41,21.71 203.45,22.67 202.18,22.67 198.44,26.42 v1(198.44,30.92)
E70_SWCLK/TCK: length 15.2
  TOP w0.14: P34.4 v1(193.29,15.2)
  L8_SIG w0.114: v2(204.24,20.91) 203.08,19.75 197.84,19.75 v1(193.29,15.2)
E70_SWDIO/TMS: length 17.6
  TOP w0.14: P34.2 v1(192.02,15.2)
  L8_SIG w0.114: v2(205.05,21.71) 204.61,21.27 204.09,21.27 202.95,20.13 196.95,20.13 v1(192.02,15.2)
E70_TARGET_RESET_N: length 1.9
  TOP w0.14: R484.2 191.71,29.85 192.22,30.36 U56.3
E70_TDI: length 16.3
  TOP w0.14: P34.8 v1(195.83,15.2)
  L8_SIG w0.114: v2(204.24,18.91) 199.44,18.91 198.55,18.02 196.62,18.02 194.02,15.43 194.02,14.83 194.22,14.63 195.26,14.63 v1(195.83,15.2)
E70_TRACESW0/TDO: length 13.5
  TOP w0.14: P34.6 v1(194.56,15.2)
  L8_SIG w0.114: v1(194.56,15.2) 196.82,17.46 198.63,17.46 199.64,18.48 204.21,18.48 v2(204.65,18.91)
E70_USBDM: length 19.3
  TOP w0.102: P9.A7 207.89,11.43 207.77,11.56 207.77,11.89 207.94,12.07 209.74,12.07 210.17,12.5 210.17,13.89 209.5,14.57 207.84,14.57 207.52,14.25 207.52,13.67 207.42,13.57 v1(207,13.57)
  BOTTOM w0.102: v2(207.45,18.11) 207.45,17.86 207.52,17.79 207.52,16.18 207,15.65 D13.1 v1(207,13.57) 207.42,13.57 207.52,13.47 207.52,10.06 207.24,9.78 P9.B7
E70_USBDP: length 19.4
  TOP w0.102: P9.A6 207.4,11.43 207.52,11.56 207.52,11.99 207.84,12.31 208.66,12.31 208.76,12.41 208.76,12.8 208.87,12.9 209.12,12.9 209.22,12.8 209.22,12.41 209.32,12.31 209.64,12.31 209.93,12.6 209.93,13.79 209.4,14.33 207.94,14.33 207.77,14.15 207.77,13.67 207.87,13.57 v1(208.29,13.57)
  BOTTOM w0.102: P9.B6 208.05,9.78 207.77,10.06 207.77,13.47 207.87,13.57 v1(208.29,13.57) D13.3 208.29,15.65 207.77,16.18 207.77,17.79 207.84,17.86 v2(207.84,18.11)
E70_VBG: length 3.1
  TOP w0.203: U54.A3 208.24,17.04 208.92,16.36 C323.1
  TOP w0.508: C323.1 R463.1
E70_VDDCORE: length 9.2
  BOTTOM w0.203: C332.1 207.45,21.33 v2(207.45,21.71) 207.45,22.99 207.45,23 C331.1
  BOTTOM w0.508: v1(201.92,21.78) C337.1 C330.1 C328.1 201.96,18.83 E4.2 ; C340.1 v1(205.64,17.46) ; v1(209.9,19.72) E5.2 211.68,19.72 211.72,19.76 C334.1
  vias: v2(205.45,20.51) v2(207.45,19.31) v2(207.84,19.71)
EEPROM_WP: length 154.3
  TOP w0.127: v1(152.46,92.01) R590.1 151.76,90.79 S15.1
  L3_SIG w0.127: v1(279.59,84.49) 271.19,92.89 248.18,92.89 241.48,86.18 235.53,86.18 229.44,80.09 225.42,80.09 212.93,92.58 153.03,92.58 v1(152.46,92.01)
  BOTTOM w0.127: v1(152.46,92.01) 152.46,84.65 152.59,84.52 U76.5
  BOTTOM w0.14: U10.5 v1(279.59,84.49)
ETH0_LINK_LED: length 25.7
  TOP w0.127: R80.2 129.66,37.47 132.33,34.8 140.33,34.8 141.09,34.04 R82.2
  TOP w0.14: R80.2 v1(130.36,39.37)
  BOTTOM w0.14: U1.21 133.01,41.19 131.19,39.37 v1(130.36,39.37) R80.2
ETH0_MD_INT_SOM_A: length 29.9
  TOP w0.127: SOMA.75 v1(132.64,64.85)
  L3_SIG w0.127: v1(132.64,64.85) 132.09,65.41 131.21,65.41 123.77,57.96 v1(123.77,42.54)
  BOTTOM w0.14: v1(123.77,42.54) U11.4
ETH0_MD_INT_Z: length 10.8
  BOTTOM w0.14: U1.22 132.36,41.69 131.45,40.77 R78.2 129.66,40.7 129.03,40.07 124.4,40.07 124.27,40.2 U11.2
ETH0_MDC_SOM_A: length 49
  TOP w0.127: SOMA.125 v1(145.14,64.78)
  L3_SIG w0.127: v1(130.36,41.85) 131.8,43.29 131.8,44.96 132.31,45.47 141.73,45.47 144.02,47.75 150.24,47.75 151.38,48.89 151.38,58.54 v1(145.14,64.78)
  BOTTOM w0.127: U1.23 130.7,42.19 v1(130.36,41.85)
  BOTTOM w0.14: R62.1 v1(130.36,41.85)
ETH0_MDIO_SOM_A: length 47.5
  TOP w0.127: SOMA.123 v1(144.65,64.27)
  L3_SIG w0.127: v1(130.36,42.93) 131.06,43.64 131.06,45.27 132,46.2 141.43,46.2 143.71,48.49 149.94,48.49 150.65,49.2 150.65,58.24 144.65,64.24 v1(144.65,64.27)
  BOTTOM w0.127: v1(130.36,42.93) 130.63,42.66 133.59,42.66 U1.24
  BOTTOM w0.14: R81.2 v1(130.36,42.93)
ETH0_MDIX_MODE: length 5
  TOP w0.127: R75.2 v1(130.36,45.09)
  BOTTOM w0.14: R75.2 v1(130.36,45.09) 131.26,44.19 U1.27
ETH0_PHY_CFG1: length 23.8
  TOP w0.127: v1(130.36,44.01) R77.2 129.66,41.14 128.65,40.13 127.76,40.13 127.25,39.62 127.25,38.74 131.96,34.03 R83.2
  BOTTOM w0.14: U1.26 130.68,43.69 v1(130.36,44.01) R77.2
ETH0_RESET*: length 188.2
  TOP w0.127: U80.2 189.97,85.2 v1(189.36,84.58) ; v1(26.64,116.41) 27.1,116.41 27.58,115.93 27.58,115.29 27.89,114.99 U8.8
  L8_SIG w0.127: v1(189.36,84.58) 189.36,84.15 188.75,83.54 153.47,83.54 150.57,86.44 128.91,86.44 128.12,87.22 115.29,87.22 115.07,86.99 111.69,86.99 111.05,86.36 103,86.36 101.98,87.38 101.98,88.65 90.93,99.69 66.37,99.69 56.13,109.93 25.76,109.93 25.1,110.59 25.1,114.86 v1(26.64,116.41)
ETH0_RESET_Z*: length 103.4
  TOP w0.127: U80.10 189.97,88.96 190.42,89.41 195.1,89.41 196.39,88.11 196.39,67.44 188.43,59.47 v1(188.43,49.65)
  L8_SIG w0.127: v1(188.43,49.65) 183.87,45.08 143.5,45.08 141.1,42.69 v1(140.16,42.69)
  BOTTOM w0.14: U1.7 v1(140.16,42.69) R68.2
ETH0_RXCLK_REFCLK_SOM_A: length 21.5
  TOP w0.127: SOMA.87 v1(135.64,64.78)
  TOP w0.14: R53.2 v1(136.14,54.41)
  L3_SIG w0.127: v1(136.14,54.41) 136.14,55.83 136.02,55.96 135.77,55.96 135.64,55.83 135.64,55.37 135.51,55.24 135.25,55.24 135.12,55.37 135.12,55.83 134.99,55.96 134.75,55.96 134.61,55.82 134.61,55.37 134.48,55.24 134.22,55.24 134.1,55.37 134.1,55.83 133.97,55.96 133.72,55.96 133.59,55.82 133.59,55.37 133.46,55.24 133.22,55.24 133.06,55.41 133.06,59.27 134.75,60.96 134.75,62.99 135.64,63.89 v1(135.64,64.78)
  BOTTOM w0.14: R65.1 v1(136.14,54.41) R53.2
ETH0_RXCTL_CRS_SOM_A: length 21.5
  TOP w0.127: v1(135.48,62.74) 137.42,62.74 138.64,63.97 SOMA.99
  TOP w0.14: R55.2 v1(137.41,54.41)
  L3_SIG w0.127: v1(137.41,54.41) 137.41,53.85 137.74,53.53 138.87,53.53 139.19,53.85 139.19,59.63 136.08,62.74 v1(135.48,62.74)
  BOTTOM w0.14: R55.2 v1(137.41,54.41) R70.1
ETH0_RXD0_SOM_A: length 21.5
  TOP w0.127: SOMA.77 v1(133.15,61.73)
  TOP w0.14: R72.2 v1(134.87,54.41)
  L3_SIG w0.127: v1(134.87,54.41) 134.87,53.85 133.73,52.7 131.44,52.7 130.68,53.47 130.68,59.27 v1(133.15,61.73)
  BOTTOM w0.14: R72.2 v1(134.87,54.41) R63.1
ETH0_RXD1_SOM_A: length 21.5
  TOP w0.127: SOMA.79 133.64,63.08 134.09,62.64 v1(134.09,62.61)
  TOP w0.14: R67.2 v1(133.6,54.41)
  L3_SIG w0.127: v1(133.6,54.41) 133.98,54.03 133.98,53.72 133.48,53.21 132.95,53.21 132.82,53.34 132.82,54.05 132.69,54.18 132.45,54.18 132.31,54.04 132.31,53.34 132.18,53.21 131.83,53.21 131.32,53.72 131.32,58.93 134.09,61.7 v1(134.09,62.61)
  BOTTOM w0.14: R67.2 v1(133.6,54.41) R64.1
ETH0_RXD2_SOM_A: length 21.4
  TOP w0.127: SOMA.81 v1(134.15,63.88)
  TOP w0.14: R61.2 v1(130.68,49.52)
  L3_SIG w0.127: v1(130.68,49.52) 130.01,50.2 130.01,50.46 130.43,50.88 130.43,51.18 130.14,51.47 130.14,51.9 130.43,52.2 130.43,52.58 130.01,53 130.01,59.75 v1(134.15,63.88)
  BOTTOM w0.14: R61.2 v1(130.68,49.52) R69.1
ETH0_RXD3_SOM_A: length 21.3
  TOP w0.127: SOMA.83 v1(134.64,64.78)
  TOP w0.14: R59.2 v1(129.54,49.52)
  L3_SIG w0.127: v1(129.54,49.52) 129.54,60.33 133.99,64.78 v1(134.64,64.78)
  BOTTOM w0.14: R73.1 v1(129.54,49.52) R59.2
ETH0_TXCLK_SOM_A: length 28.9
  TOP w0.127: SOMA.101 v1(139.15,64.27)
  L3_SIG w0.127: v1(139.15,64.27) 139.15,63.55 145.41,57.28 145.41,54.48 143.03,52.1 139.93,52.1 139.7,52.32 v1(139.7,52.83)
  BOTTOM w0.127: v1(139.7,52.83) 139.7,51.69 137.77,49.76 U1.38
ETH0_TXD0_SOM_A: length 28.9
  TOP w0.127: SOMA.89 v1(136.15,64.27)
  L3_SIG w0.127: v1(136.15,64.27) 136.15,63.34 140.84,58.64 140.84,57.81 140.66,57.62 140.01,57.62 139.83,57.43 139.83,57.17 140.01,56.99 140.66,56.99 140.84,56.8 140.84,56.54 140.66,56.35 140.01,56.35 139.83,56.16 139.83,55.9 140.01,55.72 140.66,55.72 140.84,55.53 140.84,55.27 140.66,55.08 140.01,55.08 139.83,54.89 139.83,53.85 140.08,53.59 140.59,53.59 140.84,53.85 v1(140.84,54.23)
  BOTTOM w0.127: v1(140.84,54.23) 140.84,51.82 138.28,49.25 U1.39
ETH0_TXD1_SOM_A: length 29
  TOP w0.127: SOMA.91 v1(136.64,64.78)
  L3_SIG w0.127: v1(136.64,64.78) 136.64,63.51 141.86,58.29 141.86,57.78 142.04,57.59 142.6,57.59 142.79,57.4 142.79,57.14 142.6,56.95 141.5,56.95 141.31,56.77 141.31,56.51 141.5,56.32 142.6,56.32 142.79,56.13 142.79,55.87 142.6,55.68 141.5,55.68 141.31,55.5 141.31,55.24 141.5,55.05 141.67,55.05 141.86,54.86 v1(141.86,54.23)
  BOTTOM w0.127: v1(141.86,54.23) 141.86,47.24 140.3,45.69 U1.1
ETH0_TXD2_SOM_A: length 28.9
  TOP w0.127: SOMA.93 v1(137.15,64.27)
  L3_SIG w0.127: v1(137.15,64.27) 137.15,63.77 144.02,56.9 144.02,56.61 143.89,56.49 143.56,56.49 143.43,56.36 143.43,56.11 143.57,55.98 143.89,55.98 144.02,55.85 144.02,55.35 143.86,55.19 143.68,55.19 143.36,55.51 143.18,55.51 143.01,55.34 143.01,55.15 143.32,54.83 143.32,54.65 v1(142.9,54.23)
  BOTTOM w0.127: U1.2 141.33,45.19 142.9,46.76 v1(142.9,54.23)
ETH0_TXD3_SOM_A: length 29
  TOP w0.127: SOMA.95 v1(137.64,64.78)
  L3_SIG w0.127: v1(137.64,64.78) 137.64,64.03 144.78,56.9 144.78,55.87 144.53,55.62 144.53,55.12 144.78,54.86 144.78,54.51 144.5,54.23 v1(143.95,54.23)
  BOTTOM w0.127: v1(143.95,54.23) 143.95,46.29 142.35,44.69 U1.3
ETH0_TXEN_SOM_A: length 29
  TOP w0.127: SOMA.103 v1(139.64,64.78)
  L3_SIG w0.127: v1(138.62,51.63) 143.45,51.63 146.05,54.23 146.05,57.53 139.64,63.94 v1(139.64,64.78)
  BOTTOM w0.127: v1(138.62,51.63) 137.28,50.28 U1.37
ETH1_LINK_LED: length 25.7
  TOP w0.127: R112.2 256.66,37.47 259.33,34.8 267.34,34.8 268.09,34.04 R114.2
  TOP w0.14: R112.2 v1(257.36,39.37)
  BOTTOM w0.14: U2.21 260.01,41.19 258.19,39.37 v1(257.36,39.37) R112.2
ETH1_MD_INT_SOM_B: length 30.1
  TOP w0.127: SOMB.75 v1(259.64,64.78)
  L3_SIG w0.127: v1(259.64,64.78) 259.02,65.41 258.21,65.41 250.77,57.96 v1(250.77,42.54)
  BOTTOM w0.14: v1(250.77,42.54) U12.4
ETH1_MD_INT_Z: length 10.8
  BOTTOM w0.14: U2.22 259.36,41.69 258.45,40.77 R110.2 256.66,40.7 256.03,40.07 251.4,40.07 251.27,40.2 U12.2
ETH1_MDC_SOM_B: length 49
  TOP w0.127: SOMB.125 v1(272.14,64.78)
  L3_SIG w0.127: v1(272.14,64.78) 272.18,64.78 278.38,58.57 278.38,48.89 277.24,47.75 271.02,47.75 268.73,45.47 259.31,45.47 258.8,44.96 258.8,43.29 v1(257.36,41.85)
  BOTTOM w0.127: U2.23 257.7,42.19 v1(257.36,41.85)
  BOTTOM w0.14: R94.1 v1(257.36,41.85)
ETH1_MDIO_SOM_B: length 47.5
  TOP w0.127: SOMB.123 v1(271.65,64.27)
  L3_SIG w0.127: v1(271.65,64.27) 277.65,58.27 277.65,49.2 276.94,48.49 270.71,48.49 268.43,46.2 259,46.2 258.06,45.27 258.06,43.64 v1(257.36,42.93)
  BOTTOM w0.127: U2.24 260.59,42.66 257.63,42.66 v1(257.36,42.93)
  BOTTOM w0.14: R113.2 v1(257.36,42.93)
ETH1_MDIX_MODE: length 5
  TOP w0.127: R107.2 v1(257.36,45.09)
  BOTTOM w0.14: U2.27 258.26,44.19 v1(257.36,45.09) R107.2
ETH1_PHY_CFG1: length 23.8
  TOP w0.127: R115.2 258.96,34.03 254.25,38.74 254.25,39.62 254.76,40.13 255.65,40.13 256.66,41.14 R109.2 v1(257.36,44.01)
  BOTTOM w0.14: R109.2 v1(257.36,44.01) 257.68,43.69 U2.26
ETH1_RESET*: length 94.7
  TOP w0.127: v1(190.12,84.58) 190.37,84.84 U80.3 ; v1(255.65,121.28) 255.65,120.27 255.85,120.07 U51.8
  L8_SIG w0.127: v1(255.65,121.28) 250.67,121.28 238.46,109.07 202.51,109.07 v1(201.93,109.65)
  BOTTOM w0.127: v1(190.12,84.58) 190.93,85.39 195.28,85.39 201.93,92.05 v1(201.93,109.65)
ETH1_RESET_Z*: length 134.6
  TOP w0.127: v1(187.2,50.5) 187.2,59.49 195.78,68.07 195.78,87.96 194.74,89 190.73,89 190.37,88.65 U80.9
  L8_SIG w0.127: v1(267.16,42.69) 263.88,45.97 255.52,45.97 249.43,52.07 188.77,52.07 v1(187.2,50.5)
  BOTTOM w0.14: R100.2 v1(267.16,42.69) U2.7
ETH1_RXCLK_REFCLK_SOM_B: length 21.5
  TOP w0.127: SOMB.87 v1(262.64,64.78)
  TOP w0.14: R85.2 v1(263.14,54.41)
  L3_SIG w0.127: v1(262.64,64.78) 262.64,63.89 261.75,62.99 261.75,60.96 260.06,59.27 260.06,55.41 260.22,55.24 260.46,55.24 260.59,55.37 260.59,55.82 260.72,55.96 260.97,55.96 261.1,55.83 261.1,55.37 261.22,55.24 261.48,55.24 261.61,55.37 261.61,55.82 261.75,55.96 261.99,55.96 262.12,55.83 262.12,55.37 262.25,55.24 262.51,55.24 262.64,55.37 262.64,55.83 262.77,55.96 263.02,55.96 263.14,55.83 v1(263.14,54.41)
  BOTTOM w0.14: R97.1 v1(263.14,54.41) R85.2
ETH1_RXCTL_CRS_SOM_B: length 21.5
  TOP w0.127: v1(262.48,62.74) 264.42,62.74 265.64,63.97 SOMB.99
  TOP w0.14: R87.2 v1(264.41,54.41)
  L3_SIG w0.127: v1(264.41,54.41) 264.41,53.85 264.74,53.53 265.87,53.53 266.19,53.85 266.19,59.63 263.08,62.74 v1(262.48,62.74)
  BOTTOM w0.14: R102.1 v1(264.41,54.41) R87.2
ETH1_RXD0_SOM_B: length 21.5
  TOP w0.127: SOMB.77 v1(260.15,61.73)
  TOP w0.14: R104.2 v1(261.87,54.41)
  L3_SIG w0.127: v1(260.15,61.73) 257.68,59.27 257.68,53.47 258.44,52.7 260.73,52.7 261.87,53.85 v1(261.87,54.41)
  BOTTOM w0.14: R95.1 v1(261.87,54.41) R104.2
ETH1_RXD1_SOM_B: length 21.5
  TOP w0.127: SOMB.79 260.64,63.08 261.09,62.64 v1(261.09,62.61)
  TOP w0.14: R99.2 v1(260.6,54.41)
  L3_SIG w0.127: v1(260.6,54.41) 260.99,54.03 260.99,53.72 260.48,53.21 259.95,53.21 259.82,53.34 259.82,54.05 259.69,54.18 259.45,54.18 259.31,54.04 259.31,53.34 259.18,53.21 258.83,53.21 258.32,53.72 258.32,58.93 261.09,61.7 v1(261.09,62.61)
  BOTTOM w0.14: R96.1 v1(260.6,54.41) R99.2
ETH1_RXD2_SOM_B: length 21.4
  TOP w0.127: SOMB.81 v1(261.15,63.88)
  TOP w0.14: R93.2 v1(257.68,49.52)
  L3_SIG w0.127: v1(261.15,63.88) 257.01,59.75 257.01,53 257.43,52.58 257.43,52.2 257.14,51.9 257.14,51.47 257.43,51.18 257.43,50.88 257.01,50.46 257.01,50.2 v1(257.68,49.52)
  BOTTOM w0.14: R101.1 v1(257.68,49.52) R93.2
ETH1_RXD3_SOM_B: length 21.3
  TOP w0.127: SOMB.83 v1(261.64,64.78)
  TOP w0.14: R91.2 v1(256.54,49.52)
  L3_SIG w0.127: v1(261.64,64.78) 260.99,64.78 256.54,60.33 v1(256.54,49.52)
  BOTTOM w0.14: R91.2 v1(256.54,49.52) R105.1
ETH1_TXCLK_SOM_B: length 28.9
  TOP w0.127: SOMB.101 v1(266.15,64.27)
  L3_SIG w0.127: v1(266.7,52.83) 266.7,52.32 266.93,52.1 270.03,52.1 272.42,54.48 272.42,57.28 266.15,63.55 v1(266.15,64.27)
  BOTTOM w0.127: v1(266.7,52.83) 266.7,51.69 264.77,49.76 U2.38
ETH1_TXD0_SOM_B: length 28.9
  TOP w0.127: SOMB.89 v1(263.15,64.27)
  L3_SIG w0.127: v1(263.15,64.27) 263.15,63.34 267.84,58.64 267.84,57.81 267.66,57.62 267.01,57.62 266.83,57.43 266.83,57.17 267.01,56.99 267.66,56.99 267.84,56.8 267.84,56.54 267.66,56.35 267.01,56.35 266.83,56.16 266.83,55.9 267.01,55.72 267.66,55.72 267.84,55.53 267.84,55.27 267.66,55.08 267.01,55.08 266.83,54.89 266.83,53.85 267.08,53.59 267.59,53.59 267.84,53.85 v1(267.84,54.23)
  BOTTOM w0.127: U2.39 265.28,49.25 267.84,51.82 v1(267.84,54.23)
ETH1_TXD1_SOM_B: length 29
  TOP w0.127: SOMB.91 v1(263.64,64.78)
  L3_SIG w0.127: v1(268.86,54.23) 268.86,54.86 268.67,55.05 268.5,55.05 268.31,55.24 268.31,55.5 268.5,55.68 269.6,55.68 269.79,55.87 269.79,56.13 269.6,56.32 268.5,56.32 268.31,56.51 268.31,56.77 268.5,56.95 269.6,56.95 269.79,57.14 269.79,57.4 269.6,57.59 269.04,57.59 268.86,57.78 268.86,58.29 263.64,63.51 v1(263.64,64.78)
  BOTTOM w0.127: U2.1 267.3,45.69 268.86,47.24 v1(268.86,54.23)
ETH1_TXD2_SOM_B: length 28.9
  TOP w0.127: SOMB.93 v1(264.15,64.27)
  L3_SIG w0.127: v1(269.9,54.23) 270.32,54.65 270.32,54.83 270.01,55.15 270.01,55.34 270.18,55.51 270.36,55.51 270.68,55.19 270.86,55.19 271.02,55.35 271.02,55.85 270.89,55.98 270.57,55.98 270.43,56.11 270.43,56.36 270.56,56.49 270.89,56.49 271.02,56.61 271.02,56.9 264.15,63.77 v1(264.15,64.27)
  BOTTOM w0.127: v1(269.9,54.23) 269.9,46.76 268.33,45.19 U2.2
ETH1_TXD3_SOM_B: length 29
  TOP w0.127: SOMB.95 v1(264.64,64.78)
  L3_SIG w0.127: v1(270.95,54.23) 271.5,54.23 271.78,54.51 271.78,54.86 271.53,55.12 271.53,55.62 271.78,55.87 271.78,56.9 264.64,64.03 v1(264.64,64.78)
  BOTTOM w0.127: U2.3 269.35,44.69 270.95,46.29 v1(270.95,54.23)
ETH1_TXEN_SOM_B: length 29
  TOP w0.127: SOMB.103 v1(266.64,64.78)
  L3_SIG w0.127: v1(266.64,64.78) 266.64,63.94 273.05,57.53 273.05,54.23 270.45,51.63 v1(265.62,51.63)
  BOTTOM w0.127: v1(265.62,51.63) 264.28,50.28 264.28,46.34
GPIO_00: length 37.9
  TOP w0.127: SOMA.19 118.64,61.84 108.47,51.67 94.21,51.67 P37.4
GPIO_01: length 35.9
  TOP w0.127: SOMA.21 119.15,61.63 108.68,51.16 96.25,51.16 P37.6
GPIO_02: length 34
  TOP w0.127: SOMA.23 119.64,61.42 108.89,50.67 98.29,50.67 P37.8
GPIO_03: length 32.1
  TOP w0.127: P37.10 100.33,50.16 109.09,50.16 120.15,61.22 SOMA.25
HADC_VIN0_SOM_A: length 35.8
  TOP w0.127: SOMA.74 132.39,83.12 137.39,88.12 143.26,88.12 145.54,90.4 P5.1
HADC_VIN0_SOM_B: length 33
  TOP w0.127: SOMB.74 259.39,83 264.63,88.23 265.55,88.23 272.54,95.23 P6.1
HADC_VIN1_SOM_A: length 36.6
  TOP w0.127: P5.3 148.08,98.55 146.04,96.51 146.04,90.2 143.45,87.61 137.72,87.61 132.9,82.78 SOMA.76
HADC_VIN1_SOM_B: length 33.8
  TOP w0.127: SOMB.76 259.9,82.79 264.84,87.73 265.75,87.73 275.08,97.06 P6.3
HADC_VIN2_SOM_A: length 38.1
  TOP w0.127: P5.5 150.62,98.55 149.35,97.28 148.08,97.28 146.54,95.74 146.54,89.99 143.02,86.47 137.4,86.47 133.39,82.47 SOMA.78
HADC_VIN2_SOM_B: length 34.1
  TOP w0.127: P6.5 277.62,98.89 260.39,81.67 SOMB.78
HADC_VIN3_SOM_A: length 39.9
  TOP w0.127: SOMA.80 133.9,82.11 137.75,85.97 143.23,85.97 147.04,89.78 147.04,95.48 148.34,96.77 151.38,96.77 153.16,98.55 P5.7
HADC_VIN3_SOM_B: length 36.2
  TOP w0.127: P6.7 280.16,98.55 278.38,96.77 276.21,96.77 260.9,81.46 SOMB.80
HADC_VIN4_SOM_A: length 41.8
  TOP w0.127: SOMA.82 134.39,81.77 138.09,85.47 143.44,85.47 147.54,89.57 147.54,95.22 148.59,96.27 153.42,96.27 155.7,98.55 P5.9
HADC_VIN4_SOM_B: length 38.1
  TOP w0.127: SOMB.82 261.39,81.25 276.41,96.27 280.42,96.27 282.7,98.55 P6.9
HADC_VIN5_SOM_A: length 43.6
  TOP w0.127: SOMA.84 134.9,81.57 138.3,84.97 143.65,84.97 148.04,89.37 148.04,94.83 148.97,95.76 155.45,95.76 158.24,98.55 P5.11
HADC_VIN5_SOM_B: length 40.1
  TOP w0.127: SOMB.84 261.9,81.05 276.61,95.76 282.45,95.76 285.24,98.55 P6.11
HADC_VIN6_SOM_A: length 45.4
  TOP w0.127: P5.13 160.78,98.55 157.47,95.24 149.22,95.24 148.54,94.57 148.54,89.18 143.81,84.45 138.48,84.45 135.39,81.36 SOMA.86
HADC_VIN6_SOM_B: length 42
  TOP w0.127: SOMB.86 262.39,80.86 276.78,95.24 284.47,95.24 287.78,98.55 P6.13
HADC_VIN7_SOM_A: length 47.3
  TOP w0.127: SOMA.88 135.9,81.03 138.82,83.95 144.02,83.95 149.04,88.97 149.04,94.36 149.42,94.74 159.51,94.74 163.32,98.55 P5.15
HADC_VIN7_SOM_B: length 43.9
  TOP w0.127: SOMB.88 262.9,80.65 276.99,94.74 286.51,94.74 290.32,98.55 P6.15
ID0: length 86.7
  TOP w0.127: R471.2 R472.1 201.43,23.99 204.24,26.8 204.24,28.27 206.02,30.05 217.17,30.05 222.02,34.9 222.02,47.73 220.34,49.4 220.34,61.59 224.05,65.3 224.05,76.48 225.93,78.36 235.84,78.36 237.39,79.91 U15.9
ID0_SOMA: length 70.2
  TOP w0.127: SOMA.264 v1(179.89,74.95)
  TOP w0.14: U15.10 v1(237.55,80.41)
  BOTTOM w0.127: v1(179.89,74.95) 179.89,74.43 181.04,73.28 193.75,73.28 196.34,75.87 196.34,79.04 198.93,81.64 210.82,81.64 214.86,85.67 229.59,85.67 234.85,80.41 v1(237.55,80.41)
ID0_SOMB: length 79.6
  TOP w0.127: SOMB.264 306.89,76.95 306.58,77.27 v1(306.58,77.93)
  TOP w0.14: U15.11 v1(239.43,80.91)
  L8_SIG w0.127: v1(239.43,80.91) 246.79,80.91 252.85,86.97 261.67,86.97 262.43,87.73 265.18,87.73 266.42,86.49 275.7,86.49 277.14,85.04 279.81,85.04 280.63,84.23 298.17,84.23 304.47,77.93 v1(306.58,77.93)
ID1: length 97.6
  TOP w0.127: v1(201.25,22.8) 201.77,22.8 201.93,22.63 202.59,22.63 203.2,23.24 203.2,25.07 204.6,26.47 204.6,28.19 205.92,29.51 217.42,29.51 222.53,34.62 222.53,48.49 220.98,50.04 220.98,61.47 224.56,65.05 224.56,76.35 226.02,77.81 237.58,77.81 240.11,80.34 240.11,81.1 239.8,81.41 U15.12
  TOP w0.14: R468.2 v1(201.25,22.8)
  BOTTOM w0.114: v1(201.25,22.8) 201.76,22.29 203.27,22.29 v2(205.05,20.51)
ID1_SOMA: length 70.2
  TOP w0.127: SOMA.266 v1(180.4,75.45)
  TOP w0.14: U15.13 v1(237.55,81.91)
  BOTTOM w0.127: v1(237.55,81.91) 237.09,81.46 234.49,81.46 229.82,86.13 214.3,86.13 210.36,82.19 198.73,82.19 195.76,79.22 195.76,76.05 193.5,73.79 181.34,73.79 180.4,74.73 v1(180.4,75.45)
ID1_SOMB: length 81.3
  TOP w0.127: SOMB.266 v1(307.4,77.88)
  TOP w0.14: v1(242.47,82.89) 241.5,81.91 239.52,81.91 239.03,82.41 U15.14
  L8_SIG w0.127: v1(307.4,77.88) 307.4,78.3 307.23,78.47 304.56,78.47 298.45,84.58 280.78,84.58 279.96,85.4 277.29,85.4 275.84,86.84 266.57,86.84 265.33,88.09 262.28,88.09 261.52,87.33 252.2,87.33 246.91,82.04 243.32,82.04 v1(242.47,82.89)
JTAG_1V8: length 1.6
  TOP w0.508: P10.3 227.2,24.19
JTAG_DAISY_CHAIN*: length 119
  TOP w0.127: v1(190.12,39.08) 188.85,40.35 188.85,44.53 191.64,47.32 191.64,61.72 198.07,68.15 198.07,87.83 199.57,89.33 U9.1 205.61,89.33 205.79,89.15 205.79,87.6 205.57,87.38 U9.4 202.6,87.38 202.26,87.05 202.26,84.96 202.62,84.61 211.71,84.61 211.84,84.73 211.84,86.6 211.71,86.73 U9.10 208.47,86.73 208.2,86.99 208.2,88.49 208.39,88.68 U9.13 212.54,88.68 214.16,87.06 S1.2 224.27,87.06 v1(224.74,87.53)
  TOP w0.14: U52.1 v1(235.78,90.52)
  BOTTOM w0.127: v1(235.78,90.52) 236.35,89.96 236.35,88.9 234.98,87.53 v1(224.74,87.53)
  BOTTOM w0.203: U60.10 v1(190.12,39.08)
JTAG_DAISY_CHAIN_DETECT: length 32.4
  BOTTOM w0.127: U60.7 190.77,36.16 190.28,35.66 189.61,35.66 188.54,34.59 188.54,31.98 189.53,30.99 196.55,30.99 197.46,31.9 203.29,31.9 204.71,30.48 204.71,26.29 205.86,25.15 208.4,25.15 208.52,25.02 208.53,25.02 R599.2
